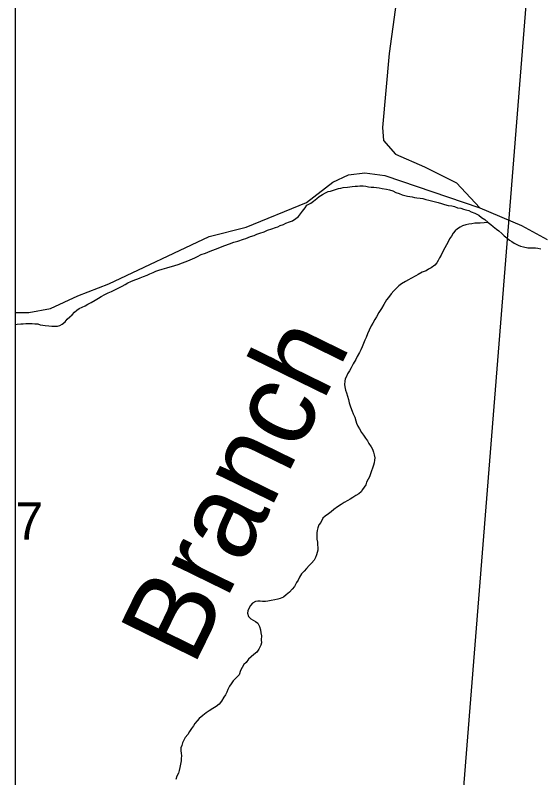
# Model space of a CAD drawing. Extents: x 0.4 to 34.4, y -2.1 to 19.9.
# Drawn here: x 3 to 3.589, y 15.936 to 16.79 of the extents above; entities that cross this region are included whole.
import ezdxf

# ---------------------------------------------------------------- set-up
doc = ezdxf.new("R2010")
doc.units = 0
for name, color, linetype in [('GM_X_County', 7, 'Continuous'), ('GM_X_County_Road', 7, 'Continuous'), ('GM_X_Minor_River', 7, 'Continuous'), ('GM_X_Minor_River_Text', 7, 'Continuous'), ('GM_X_Section', 7, 'Continuous'), ('GM_X_Section_Text', 7, 'Continuous'), ('GM_X_Township', 7, 'Continuous'), ('GM_X_Township_Road', 7, 'Continuous'), ('SH_Data', 7, 'Continuous')]:
    doc.layers.add(name, color=color, linetype=linetype)

msp = doc.modelspace()

# ---------------------------------------------------------------- linework, layer by layer
at = {"layer": 'GM_X_County'}
msp.add_lwpolyline([(9.80012, 15.3423), (9.80012, 18.83567), (3.00012, 18.83567), (3.00012, 12.03567), (9.50737, 12.03567)], dxfattribs=at)
at = {"layer": 'GM_X_County_Road'}
msp.add_lwpolyline([(3.00012, 16.45702), (3.01529, 16.45709), (3.03971, 16.46165), (3.0703, 16.47588), (3.10501, 16.48942), (3.21734, 16.54215), (3.25892, 16.55262), (3.32649, 16.58048), (3.35606, 16.60306), (3.37377, 16.61138), (3.39175, 16.6138), (3.41429, 16.61084), (3.52081, 16.57435), (3.56748, 16.55452), (3.59639, 16.53895)], dxfattribs=at)
at = {"layer": 'GM_X_Minor_River'}
for points in [[(3.22049, 16.52673), (3.22549, 16.52854), (3.2301, 16.53036), (3.2351, 16.53217), (3.2401, 16.53398), (3.24511, 16.53617), (3.2497, 16.53723), (3.25585, 16.5394), (3.25854, 16.54011), (3.26123, 16.5412), (3.26393, 16.54229), (3.26776, 16.54337), (3.27085, 16.54483), (3.2743, 16.54591), (3.27892, 16.54773), (3.28277, 16.54956), (3.28776, 16.55099), (3.29161, 16.55244), (3.29429, 16.55315), (3.29699, 16.55462), (3.30083, 16.5557), (3.30353, 16.55717), (3.30737, 16.55862), (3.31084, 16.56007), (3.31471, 16.56267), (3.31743, 16.5649), (3.31978, 16.5679), (3.32214, 16.5709), (3.32488, 16.57428), (3.32686, 16.57728), (3.33149, 16.57986), (3.33421, 16.58209), (3.33809, 16.58507), (3.34081, 16.5873), (3.34429, 16.58952), (3.34776, 16.59136), (3.35085, 16.59282), (3.35352, 16.59315), (3.3589, 16.59496), (3.36236, 16.59603), (3.36503, 16.59636), (3.36772, 16.59708), (3.37231, 16.59775), (3.37499, 16.59808), (3.37766, 16.59842), (3.3811, 16.59873), (3.38377, 16.59868), (3.38644, 16.59902), (3.38987, 16.59895), (3.39292, 16.5989), (3.39595, 16.59808), (3.399, 16.59764), (3.40204, 16.59759), (3.40508, 16.59715), (3.40812, 16.59672), (3.41117, 16.59628), (3.4161, 16.59543), (3.41951, 16.59461), (3.4233, 16.5934), (3.4267, 16.59181), (3.43048, 16.5906), (3.43388, 16.58902), (3.43691, 16.5882), (3.43956, 16.58739), (3.44489, 16.58691), (3.44754, 16.5861), (3.4502, 16.58568), (3.454, 16.58522), (3.45704, 16.58479), (3.46045, 16.58396), (3.46349, 16.58315), (3.46652, 16.58233), (3.46955, 16.58152), (3.47409, 16.58029), (3.47789, 16.57946), (3.48129, 16.57826), (3.48546, 16.57704), (3.48926, 16.57659), (3.49229, 16.57577), (3.4957, 16.57457), (3.4995, 16.57412), (3.50252, 16.57292), (3.50518, 16.57211), (3.50859, 16.57129), (3.51123, 16.5701), (3.51501, 16.56851), (3.51953, 16.56614), (3.52253, 16.56381), (3.52629, 16.56146), (3.53002, 16.55796), (3.53302, 16.55563), (3.53564, 16.55368), (3.53939, 16.55057), (3.54201, 16.54861), (3.54537, 16.54551), (3.54799, 16.54318), (3.55099, 16.54084), (3.55397, 16.53812), (3.55661, 16.53655), (3.55924, 16.53498), (3.56376, 16.53262)], [(3.53002, 16.55796), (3.52124, 16.55736), (3.51857, 16.55741), (3.51513, 16.5571), (3.51168, 16.5564), (3.50863, 16.55607), (3.50518, 16.55538), (3.50134, 16.5543), (3.49864, 16.55283), (3.49593, 16.55098), (3.49321, 16.54875), (3.49086, 16.54613), (3.48888, 16.54274), (3.48691, 16.53973), (3.48491, 16.53558), (3.48332, 16.53295), (3.48172, 16.52955), (3.47934, 16.52541), (3.47734, 16.52127), (3.47575, 16.51825), (3.47417, 16.51562), (3.47258, 16.51298), (3.47023, 16.51036), (3.46635, 16.50739), (3.46326, 16.50555), (3.46055, 16.50369), (3.45632, 16.50225), (3.45169, 16.49967), (3.44899, 16.4982), (3.44359, 16.49525), (3.44088, 16.49378), (3.43741, 16.49194), (3.43316, 16.48936), (3.43006, 16.48713), (3.42694, 16.48414), (3.42459, 16.48153), (3.42147, 16.47816), (3.41833, 16.47403), (3.41636, 16.4714), (3.41478, 16.46877), (3.41319, 16.46614), (3.41042, 16.46162), (3.40765, 16.45711), (3.40487, 16.45221), (3.40328, 16.4492), (3.4009, 16.44506), (3.39892, 16.44205), (3.39692, 16.43752), (3.39492, 16.43337), (3.3933, 16.42922), (3.39209, 16.4262), (3.39047, 16.42242), (3.38886, 16.41865), (3.38726, 16.41525), (3.38605, 16.41223), (3.38328, 16.40772), (3.38168, 16.40432), (3.37891, 16.39981), (3.37652, 16.39528), (3.37454, 16.3919), (3.37256, 16.38851), (3.37134, 16.38549), (3.36976, 16.38285), (3.36932, 16.3802), (3.36923, 16.3764), (3.36955, 16.37373), (3.37024, 16.37029), (3.37131, 16.36723), (3.37237, 16.3634), (3.37343, 16.35958), (3.37449, 16.35575), (3.37592, 16.35154), (3.37771, 16.34657), (3.37879, 16.3435), (3.38061, 16.34004), (3.38166, 16.33584), (3.38275, 16.33316), (3.3842, 16.32971), (3.38603, 16.32663), (3.38824, 16.32278), (3.39045, 16.3197), (3.39266, 16.31624), (3.39488, 16.31315), (3.39635, 16.31046), (3.39893, 16.30661), (3.40039, 16.30392), (3.40146, 16.30048), (3.40254, 16.29779), (3.40323, 16.29435), (3.40279, 16.2917), (3.40234, 16.28867), (3.40151, 16.28602), (3.40068, 16.28261), (3.39946, 16.27959), (3.39824, 16.27618), (3.39703, 16.27316), (3.39583, 16.27052), (3.39385, 16.26714), (3.39302, 16.26411), (3.39105, 16.26148), (3.38947, 16.25885)], [(3.56376, 16.53262), (3.56641, 16.53143), (3.56982, 16.5306), (3.57476, 16.52975), (3.57933, 16.52967), (3.58314, 16.5296), (3.5858, 16.52917), (3.58921, 16.52835)], [(3.00012, 16.44374), (3.00245, 16.44399), (3.00627, 16.4443), (3.00895, 16.44463), (3.012, 16.44495), (3.01543, 16.44489), (3.01925, 16.44482), (3.02191, 16.44439), (3.02534, 16.44433), (3.02799, 16.44352), (3.03103, 16.44308), (3.03369, 16.44265), (3.03787, 16.4422), (3.04129, 16.44175), (3.04472, 16.44169), (3.0474, 16.44202), (3.05008, 16.44273), (3.05278, 16.44421), (3.05589, 16.44681), (3.05825, 16.44981), (3.06136, 16.45242), (3.06407, 16.45465), (3.06643, 16.45765), (3.06915, 16.45989), (3.07186, 16.46174), (3.07494, 16.4632), (3.07841, 16.46466), (3.0815, 16.46651), (3.08535, 16.46834), (3.08961, 16.47092), (3.09347, 16.47313), (3.09656, 16.47498), (3.10042, 16.47719), (3.10428, 16.47902), (3.10813, 16.48085), (3.11237, 16.48306), (3.117, 16.48526), (3.12008, 16.48672), (3.12317, 16.48857), (3.12626, 16.49041), (3.12973, 16.49187), (3.13396, 16.4937), (3.13742, 16.49478), (3.14011, 16.49587), (3.14396, 16.49732), (3.14781, 16.49915), (3.15089, 16.50061), (3.15474, 16.50207), (3.15782, 16.50353), (3.1609, 16.50462), (3.16473, 16.50569), (3.16742, 16.5064), (3.1701, 16.50711), (3.17356, 16.50819), (3.17778, 16.50963), (3.18393, 16.51142), (3.18662, 16.51252), (3.19162, 16.51433), (3.19623, 16.51614), (3.20124, 16.51834), (3.20432, 16.5198), (3.20857, 16.522), (3.21318, 16.52382), (3.21588, 16.52491), (3.22049, 16.52673)], [(3.38947, 16.25885), (3.38788, 16.25621), (3.38516, 16.25398), (3.38169, 16.25214), (3.37859, 16.24991), (3.3755, 16.24807), (3.3728, 16.2466), (3.36893, 16.24438), (3.36545, 16.24217), (3.36119, 16.2392), (3.35731, 16.23623), (3.3542, 16.23362), (3.3511, 16.23139), (3.34761, 16.22879), (3.34489, 16.22656), (3.3425, 16.22166), (3.34053, 16.21903), (3.33932, 16.21601), (3.33849, 16.21298), (3.33805, 16.21033), (3.33796, 16.20653), (3.33827, 16.2031), (3.33895, 16.19966), (3.33888, 16.19662), (3.33921, 16.19395), (3.33914, 16.1909), (3.33832, 16.18825), (3.33787, 16.1856), (3.33666, 16.18258), (3.33507, 16.17956), (3.33232, 16.17619), (3.3296, 16.17358), (3.32647, 16.17021), (3.32374, 16.16722), (3.321, 16.16422), (3.31863, 16.16046), (3.31703, 16.15707), (3.31544, 16.15443), (3.31305, 16.14991), (3.31032, 16.14692), (3.30758, 16.14392), (3.30369, 16.14057), (3.30058, 16.13796), (3.29712, 16.1365), (3.29443, 16.13579), (3.29099, 16.13509), (3.28678, 16.13441), (3.28333, 16.13371), (3.28065, 16.13338), (3.27722, 16.13344), (3.27456, 16.1335), (3.27189, 16.13354), (3.26921, 16.13321), (3.26612, 16.13136), (3.26377, 16.12875), (3.26179, 16.12536), (3.26097, 16.12271), (3.26053, 16.12005), (3.2616, 16.11661), (3.2642, 16.1139), (3.26684, 16.11233), (3.26947, 16.11076), (3.2721, 16.10881), (3.27393, 16.10535), (3.27498, 16.10153), (3.27529, 16.0981), (3.27597, 16.09466), (3.27588, 16.09047), (3.27618, 16.08705), (3.27536, 16.0844), (3.27297, 16.07988), (3.27099, 16.07649), (3.2675, 16.07389), (3.26439, 16.07128), (3.26166, 16.06867), (3.25891, 16.06491), (3.25619, 16.06268), (3.25261, 16.0559), (3.25097, 16.05098), (3.24434, 16.04425), (3.24198, 16.04087), (3.24039, 16.03824), (3.2384, 16.03447), (3.2372, 16.03183), (3.23561, 16.02881), (3.23402, 16.02618), (3.23125, 16.02167), (3.22851, 16.01829), (3.2254, 16.01568), (3.22153, 16.01347), (3.21728, 16.01089), (3.21418, 16.00866), (3.2103, 16.00569), (3.20642, 16.00233), (3.20407, 15.99971), (3.20133, 15.99672), (3.19975, 15.99409), (3.19778, 15.99108), (3.19541, 15.9877), (3.19343, 15.98431), (3.19069, 15.98093)], [(3.19069, 15.98093), (3.18909, 15.97792), (3.1875, 15.9749), (3.18667, 15.97187), (3.18585, 15.96923), (3.18577, 15.9658), (3.18609, 15.96314), (3.18641, 15.96046), (3.18596, 15.95743), (3.1859, 15.95477), (3.18544, 15.95097), (3.18459, 15.94718), (3.18375, 15.94377), (3.18292, 15.94074), (3.18132, 15.93735), (3.1801, 15.93395)]]:
    msp.add_lwpolyline(points, dxfattribs=at)
at = {"layer": 'GM_X_Section'}
msp.add_line((3.00012, 16.8828), (3.00012, 15.59238), dxfattribs=at)
for points in [[(3.00012, 15.59238), (3.29409, 15.56612), (3.47294, 15.55052), (3.57551, 16.83477), (3.00012, 16.8828)], [(3.47294, 15.55052), (3.57551, 16.83477)]]:
    msp.add_lwpolyline(points, dxfattribs=at)
at = {"layer": 'GM_X_Township'}
msp.add_line((3.00012, 17.934), (3.00012, 12.51911), dxfattribs=at)
at = {"layer": 'GM_X_Township_Road'}
msp.add_lwpolyline([(3.00012, 17.04711), (3.06206, 17.04127), (3.07051, 17.04016), (3.08318, 17.04327), (3.11587, 17.06329), (3.12544, 17.06529), (3.13744, 17.06462), (3.26219, 17.05306), (3.31445, 17.04083), (3.42252, 17.01058), (3.43608, 17.00413), (3.44231, 16.99146), (3.44632, 16.94632), (3.41906, 16.74761), (3.41173, 16.66462), (3.41294, 16.65002), (3.4263, 16.6345), (3.45883, 16.6205), (3.49478, 16.60252), (3.52081, 16.57435)], dxfattribs=at)
at = {"layer": 'SH_Data'}
msp.add_line((3.00012, 18.83567), (3.00012, 12.03567), dxfattribs=at)

# ---------------------------------------------------------------- texts
at = {"layer": 'GM_X_Minor_River_Text'}
msp.add_text('Branch', height=0.094698, rotation=63.93648, dxfattribs=at).set_placement((3.19983, 16.0593))
at = {"layer": 'GM_X_Section_Text'}
msp.add_text('7', height=0.04186, rotation=0.00001, dxfattribs=at).set_placement((3.00022, 16.20271))

doc.saveas('drawing.dxf')
